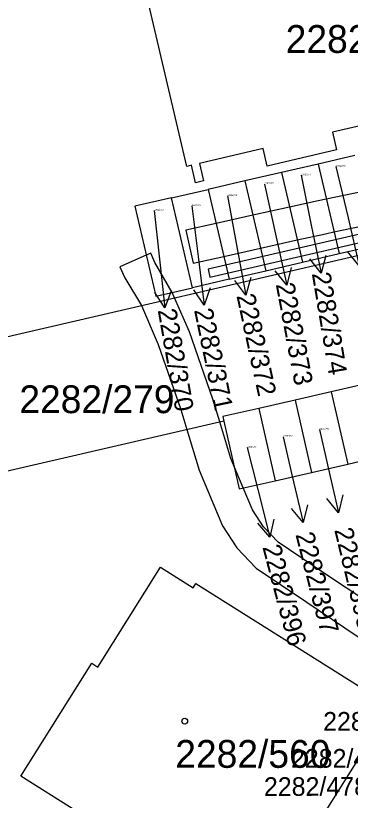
# Model space of a CAD drawing. Extents: x -785744 to -782822, y -1067550 to -1063910.
# Drawn here: x -783918.7 to -783898.25, y -1066019.89 to -1065971.96 of the extents above; entities that cross this region are included whole.
import ezdxf

# ---------------------------------------------------------------- set-up
doc = ezdxf.new("R2010")
doc.units = 0
for name, color, linetype in [('Hranice parcel', 7, 'Continuous'), ('Parcelní čísla', 7, 'Continuous'), ('Pop_ČP_popisy', 7, 'Continuous'), ('Věcná břemena k části', 7, 'Continuous'), ('Značky budov', 7, 'Continuous')]:
    doc.layers.add(name, color=color, linetype=linetype)

msp = doc.modelspace()

# ---------------------------------------------------------------- linework, layer by layer
at = {"layer": 'Hranice parcel'}
for p, q in [((-783908.25, -1065981.16), (-783911.84, -1065965.77)), ((-783895.4, -1065978.16), (-783899.34, -1065979.08)), ((-783899.34, -1065979.08), (-783899.09, -1065980.15)), ((-783903.58, -1065980.07), (-783907.47, -1065980.98)), ((-783903.33, -1065981.14), (-783903.58, -1065980.07)), ((-783899.09, -1065980.15), (-783903.33, -1065981.14)), ((-783897.98, -1065980.5), (-783900.22, -1065981.02)), ((-783907.96, -1065981.09), (-783908.25, -1065981.16)), ((-783907.71, -1065982.16), (-783907.96, -1065981.09)), ((-783907.47, -1065980.98), (-783907.22, -1065982.05)), ((-783900.22, -1065981.02), (-783902.46, -1065981.53)), ((-783900.22, -1065981.02), (-783898.94, -1065986.49)), ((-783902.46, -1065981.53), (-783904.7, -1065982.05)), ((-783902.46, -1065981.53), (-783901.18, -1065987.02)), ((-783907.22, -1065982.05), (-783907.71, -1065982.16)), ((-783904.7, -1065982.05), (-783906.94, -1065982.57)), ((-783904.7, -1065982.05), (-783903.42, -1065987.54)), ((-783909.18, -1065983.09), (-783906.94, -1065982.57)), ((-783906.94, -1065982.57), (-783905.66, -1065988.06)), ((-783909.18, -1065983.09), (-783911.42, -1065983.6)), ((-783907.9, -1065988.58), (-783909.18, -1065983.09)), ((-783911.42, -1065983.6), (-783910.14, -1065989.1)), ((-783953.96, -1065999.6), (-783890.63, -1065984.95)), ((-783898.94, -1065986.49), (-783896.7, -1065985.97)), ((-783901.18, -1065987.02), (-783898.94, -1065986.49)), ((-783903.42, -1065987.54), (-783901.18, -1065987.02)), ((-783905.66, -1065988.06), (-783903.42, -1065987.54)), ((-783905.66, -1065988.06), (-783907.9, -1065988.58)), ((-783910.14, -1065989.1), (-783907.9, -1065988.58)), ((-783897.21, -1065994.43), (-783899.42, -1065994.93)), ((-783899.42, -1065994.93), (-783901.63, -1065995.44)), ((-783899.42, -1065994.93), (-783898.41, -1065999.35)), ((-783901.63, -1065995.44), (-783903.85, -1065995.95)), ((-783901.63, -1065995.44), (-783900.63, -1065999.86)), ((-783903.85, -1065995.95), (-783906.05, -1065996.45)), ((-783903.85, -1065995.95), (-783902.84, -1066000.37)), ((-783906.05, -1065996.45), (-783905.99, -1065996.72)), ((-783905.99, -1065996.72), (-783951.31, -1066007.2)), ((-783905.99, -1065996.72), (-783905.04, -1066000.87)), ((-783898.41, -1065999.35), (-783896.2, -1065998.85)), ((-783900.63, -1065999.86), (-783898.41, -1065999.35)), ((-783902.84, -1066000.37), (-783900.63, -1065999.86)), ((-783905.04, -1066000.87), (-783902.84, -1066000.37)), ((-783913.68, -1066011.76), (-783909.85, -1066005.66)), ((-783909.85, -1066005.66), (-783907.86, -1066006.91)), ((-783907.86, -1066006.91), (-783907.69, -1066006.65)), ((-783907.69, -1066006.65), (-783897.75, -1066012.91)), ((-783918.39, -1066018.42), (-783914.06, -1066011.52)), ((-783914.06, -1066011.52), (-783913.68, -1066011.76)), ((-783895.92, -1066014.42), (-783899.75, -1066020.51)), ((-783915.03, -1066020.54), (-783918.39, -1066018.42))]:
    msp.add_line(p, q, dxfattribs=at)
at = {"layer": 'Pop_ČP_popisy'}
for p, q in [((-783898.39, -1065984.31), (-783897.701, -1065987.23)), ((-783900.64, -1065984.75), (-783900.043, -1065987.69)), ((-783902.79, -1065985.49), (-783902.141, -1065988.419)), ((-783905.18, -1065986.08), (-783904.632, -1065989.029)), ((-783909.92, -1065986.83), (-783909.585, -1065989.811)), ((-783907.56, -1065986.66), (-783907.186, -1065989.637)), ((-783899.64, -1065999.4), (-783898.972, -1066002.325)), ((-783901.82, -1066000), (-783901.138, -1066002.921)), ((-783903.91, -1066000.9), (-783903.175, -1066003.809))]:
    msp.add_line(p, q, dxfattribs=at)
for points in [[(-783899.13, -1065981.18), (-783898.39, -1065984.31)], [(-783901.26, -1065981.7), (-783900.64, -1065984.75)], [(-783903.5, -1065982.24), (-783902.79, -1065985.49)], [(-783905.75, -1065982.97), (-783905.18, -1065986.08)], [(-783907.94, -1065983.58), (-783907.56, -1065986.66)], [(-783910.25, -1065983.86), (-783909.92, -1065986.83)], [(-783897.444, -1065986.142), (-783897.701, -1065987.23), (-783898.417, -1065986.371)], [(-783899.752, -1065986.611), (-783900.043, -1065987.69), (-783900.732, -1065986.809)], [(-783901.869, -1065987.334), (-783902.141, -1065988.419), (-783902.845, -1065987.551)], [(-783904.323, -1065987.955), (-783904.632, -1065989.029), (-783905.306, -1065988.138)], [(-783909.2, -1065988.762), (-783909.585, -1065989.811), (-783910.194, -1065988.873)], [(-783906.815, -1065988.582), (-783907.186, -1065989.637), (-783907.807, -1065988.707)], [(-783900.13, -1065997.24), (-783899.64, -1065999.4)], [(-783902.36, -1065997.68), (-783901.82, -1066000)], [(-783904.56, -1065998.34), (-783903.91, -1066000.9)], [(-783898.707, -1066001.239), (-783898.972, -1066002.325), (-783899.682, -1066001.461)], [(-783900.878, -1066001.834), (-783901.138, -1066002.921), (-783901.852, -1066002.061)], [(-783902.935, -1066002.716), (-783903.175, -1066003.809), (-783903.905, -1066002.962)]]:
    msp.add_lwpolyline(points, dxfattribs=at)
at = {"layer": 'Věcná břemena k části'}
for p, q in [((-783910.72, -1065986.59), (-783912.33, -1065987.31)), ((-783910.45, -1065986.47), (-783910.72, -1065986.59)), ((-783910.2, -1065987.03), (-783910.45, -1065986.47)), ((-783909.14, -1065988.87), (-783910.2, -1065987.03)), ((-783912.33, -1065987.31), (-783912.04, -1065987.97)), ((-783912.04, -1065987.97), (-783911.01, -1065989.67)), ((-783908.99, -1065989.2), (-783909.14, -1065988.87)), ((-783908.08, -1065991.28), (-783908.99, -1065989.2)), ((-783911.01, -1065989.67), (-783910, -1065992.04)), ((-783906.65, -1065995.38), (-783908.08, -1065991.28)), ((-783910, -1065992.04), (-783908.61, -1065996.02)), ((-783906.23, -1065996.78), (-783906.65, -1065995.38)), ((-783908.61, -1065996.02), (-783908.25, -1065997.24)), ((-783905.56, -1065999.02), (-783906.23, -1065996.78)), ((-783908.25, -1065997.24), (-783907.5, -1065999.72)), ((-783905.35, -1065999.5), (-783905.56, -1065999.02)), ((-783904.8, -1066000.81), (-783905.35, -1065999.5)), ((-783907.5, -1065999.72), (-783906.06, -1066003.12)), ((-783904.24, -1066002.14), (-783904.8, -1066000.81)), ((-783903.56, -1066003.19), (-783904.24, -1066002.14)), ((-783906.06, -1066003.12), (-783905.18, -1066004.47)), ((-783902.66, -1066004.13), (-783903.56, -1066003.19)), ((-783899.82, -1066006.03), (-783902.66, -1066004.13)), ((-783905.18, -1066004.47), (-783904, -1066005.71)), ((-783904, -1066005.71), (-783900.98, -1066007.75)), ((-783896.65, -1066008.16), (-783899.82, -1066006.03)), ((-783900.98, -1066007.75), (-783897.77, -1066009.9))]:
    msp.add_line(p, q, dxfattribs=at)
for points in [[(-783897.47, -1065982.7), (-783899.72, -1065983.16)], [(-783900.21, -1065983.26), (-783901.96, -1065983.65)], [(-783899.72, -1065983.16), (-783900.21, -1065983.26)], [(-783901.96, -1065983.65), (-783904.21, -1065984.15)], [(-783891.05, -1065983.77), (-783906.95, -1065987.45)], [(-783906.84, -1065987.94), (-783889.63, -1065983.96)], [(-783904.21, -1065984.15), (-783906.45, -1065984.65)], [(-783906.45, -1065984.65), (-783908.3, -1065985.07)], [(-783899.25, -1065985.17), (-783897, -1065984.7)], [(-783908.3, -1065985.07), (-783907.85, -1065987.08)], [(-783899.77, -1065985.28), (-783899.25, -1065985.17)], [(-783903.74, -1065986.16), (-783901.5, -1065985.66)], [(-783901.5, -1065985.66), (-783899.77, -1065985.28)], [(-783905.99, -1065986.66), (-783903.74, -1065986.16)], [(-783907.85, -1065987.08), (-783905.99, -1065986.66)], [(-783906.95, -1065987.45), (-783906.84, -1065987.94)]]:
    msp.add_lwpolyline(points, dxfattribs=at)
at = {"layer": 'Značky budov'}
msp.add_circle((-783908.37, -1066015.06), 0.175, dxfattribs=at)

# ---------------------------------------------------------------- texts
at = {"layer": 'Parcelní čísla'}
for s, height, p in [('2282/346', 1.7, (-783902.2, -1065974.23)), ('2282/375', 0.1, (-783899.13, -1065981.18)), ('2282/374', 0.1, (-783901.26, -1065981.7)), ('2282/373', 0.1, (-783903.5, -1065982.24)), ('2282/372', 0.1, (-783905.75, -1065982.97)), ('2282/371', 0.1, (-783907.94, -1065983.58)), ('2282/370', 0.1, (-783910.25, -1065983.86)), ('2282/279', 1.7, (-783918.48, -1065996.24)), ('2282/398', 0.1, (-783900.13, -1065997.24)), ('2282/397', 0.1, (-783902.36, -1065997.68)), ('2282/396', 0.1, (-783904.56, -1065998.34)), ('2282/560', 1.7, (-783908.95, -1066017.91))]:
    msp.add_text(s, height=height, dxfattribs=at).set_placement(p)
at = {"layer": 'Pop_ČP_popisy'}
for s, rotation, p in [('2282/374', 279.5312, (-783900.608, -1065987.708)), ('2282/373', 280.6472, (-783902.813, -1065988.369)), ('2282/372', 282.2439, (-783905.216, -1065989.066)), ('2282/370', 279.9785, (-783910.027, -1065989.947)), ('2282/371', 281.7576, (-783907.807, -1065989.944)), ('2282/398', 283.4668, (-783899.237, -1066003.37)), ('2282/397', 284.3843, (-783901.612, -1066003.658)), ('2282/396', 284.8166, (-783903.633, -1066004.422)), ('2282/478', 0.1176, (-783903.53, -1066019.627))]:
    msp.add_text(s, height=1.14, rotation=rotation, dxfattribs=at).set_placement(p)
for s, p in [('2282/480', (-783899.913, -1066015.64)), ('2282/479', (-783901.878, -1066017.9))]:
    msp.add_text(s, height=1.14, dxfattribs=at).set_placement(p)

doc.saveas('drawing.dxf')
